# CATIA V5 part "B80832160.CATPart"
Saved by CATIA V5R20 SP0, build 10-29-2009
Part number: B80832160
Revision: 2
Definition: design
Nomenclature: B80832160
Source: made
Description: NOT SPECIFIED
Bounding box of the stored display mesh (mm): x -18.312 to 18.312, y -18.5 to 18.5, z 0 to 160
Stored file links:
  C:\Users\Raffaele\Desktop\3D X SITO CF\BOLEX\4-PILLAR REF 808\B80832160.CATPart
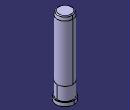
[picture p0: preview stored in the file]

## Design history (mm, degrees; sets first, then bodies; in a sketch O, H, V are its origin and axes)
Body1 "MANIFOLD_SOLID_BREP #450" (main body)
  Solid1: solid without history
